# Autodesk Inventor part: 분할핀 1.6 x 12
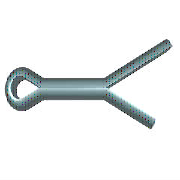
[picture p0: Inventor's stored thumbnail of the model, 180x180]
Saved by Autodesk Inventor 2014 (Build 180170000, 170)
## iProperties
IsCustomPart: 1
Created: 2012-02
Part Number: 분할핀 1.6 x 12
Material: 강철, 연강
Description: 분할 핀
Document SubType Name: Modeling
Standard: KS B 1321
Designer: mduedu
Standards Organization: KS
Language: ko-KR
Size Designation: 1.6 x  12
Categories: <MemberInstance><Categories><Category DisplayName="조임쇠" InternalName="e4da775c-781d-43d5-af7c-5136215cf5a6" Mnemonic="FSTN"><Category DisplayName="핀" InternalNa
Density: 1 g/cm^3
Appearance: 강철
Author: mduedu
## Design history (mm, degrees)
sketch "스케치1"
  geometry: L1 (0, 0.7)-(7, 0.7); L2 (0, -0.7)-(7, -0.7); L3 (7, 0.7)-(12, 2.616); L4 (12, 2.616)-(12.234, 2.005); L5 (12.234, 2.005)-(7, 0); L6 (7, 0)-(14.734, -2.963); L7 (14.734, -2.963)-(14.5, -3.573); L8 (14.5, -3.573)-(7, -0.7); L9 (0, 0)-(-1.528, -0.645); L10 (0, 0)-(-1.528, 0.645); L11 (0, 0.7)-(0, -0.7); L12 (0, 0.7)-(-1.204, 1.267); L13 (0, -0.7)-(-1.204, -1.267); L14 (-3.2, 0)-(7, 0); L15 (7, 0.7)-(7, -0.7); A1 r 1.4 centre (-1.8, 0) between (-1.204, 1.267) and (-1.204, -1.267); A2 r 0.7 centre (-1.8, 0) between (-1.528, 0.645) and (-1.528, -0.645); 1 further point
  constraints: 30 end point, 5 point on circle, 4 parallel, 4 perpendicular, 4 point on line, 4 tangent, 2 centre point, 2 midpoint, 1 coincident, 1 horizontal
  dimensions: "d0" = 7 distance of L1.start L1.end (= MSIAB); "d1" = 12 horizontal distance of L1.start L3.end (= SNLG); "d2" = 159.037 deg angle of L1 L3; "d3" = 159.037 deg angle of L2 L8; "d4" = 2.5 horizontal distance of L3.end L7.end (= LGDIF); "d5" = 0.7 radius of A2 (= -0.5 x SNND1 + 0.5 x KBR); "d6" = 1.4 radius of A1 (= 0.5 x KBR); "d7" = 0.7 distance from line of L1 L9.start (= 0.5 x SNND1); "d8" = 0.7 distance between parallel lines of L2 L14 (= 0.5 x SNND1); "d9" = 1.8 distance from line of L11 A1.centre (= KOL - 0.5 x KBR)
extrude "본체" new body sketch "스케치1" stored distance "d10" = 1.4 (= SNND1); taper "d11" = 0 deg
workaxis "Work Axis1"
workplane "Work Plane1"
workplane "Work Plane3"
body "Solid1"
fillet "모깎기" dims "d12" = 0.49 (= 0.35 x SNND1)
other parameters: "SNND" = 1.6 [user parameter], "SNLG" = 12 [user parameter; used in 1 equation term], "SNND1" = 1.4 [user parameter; used in 5 equation terms], "KBR" = 2.8 [user parameter; used in 3 equation terms], "KOL" = 3.2 [user parameter; used in 1 equation term], "LGDIF" = 2.5 [user parameter; used in 1 equation term], "MSIAB" = 7 [user parameter; used in 1 equation term], "d15" = 0, "d16" = 0, "d17" = 0, "NNDMAX" = 7 [user parameter], "DSH" = 6 [user parameter], "NNDMIN" = 5.5 [user parameter]
